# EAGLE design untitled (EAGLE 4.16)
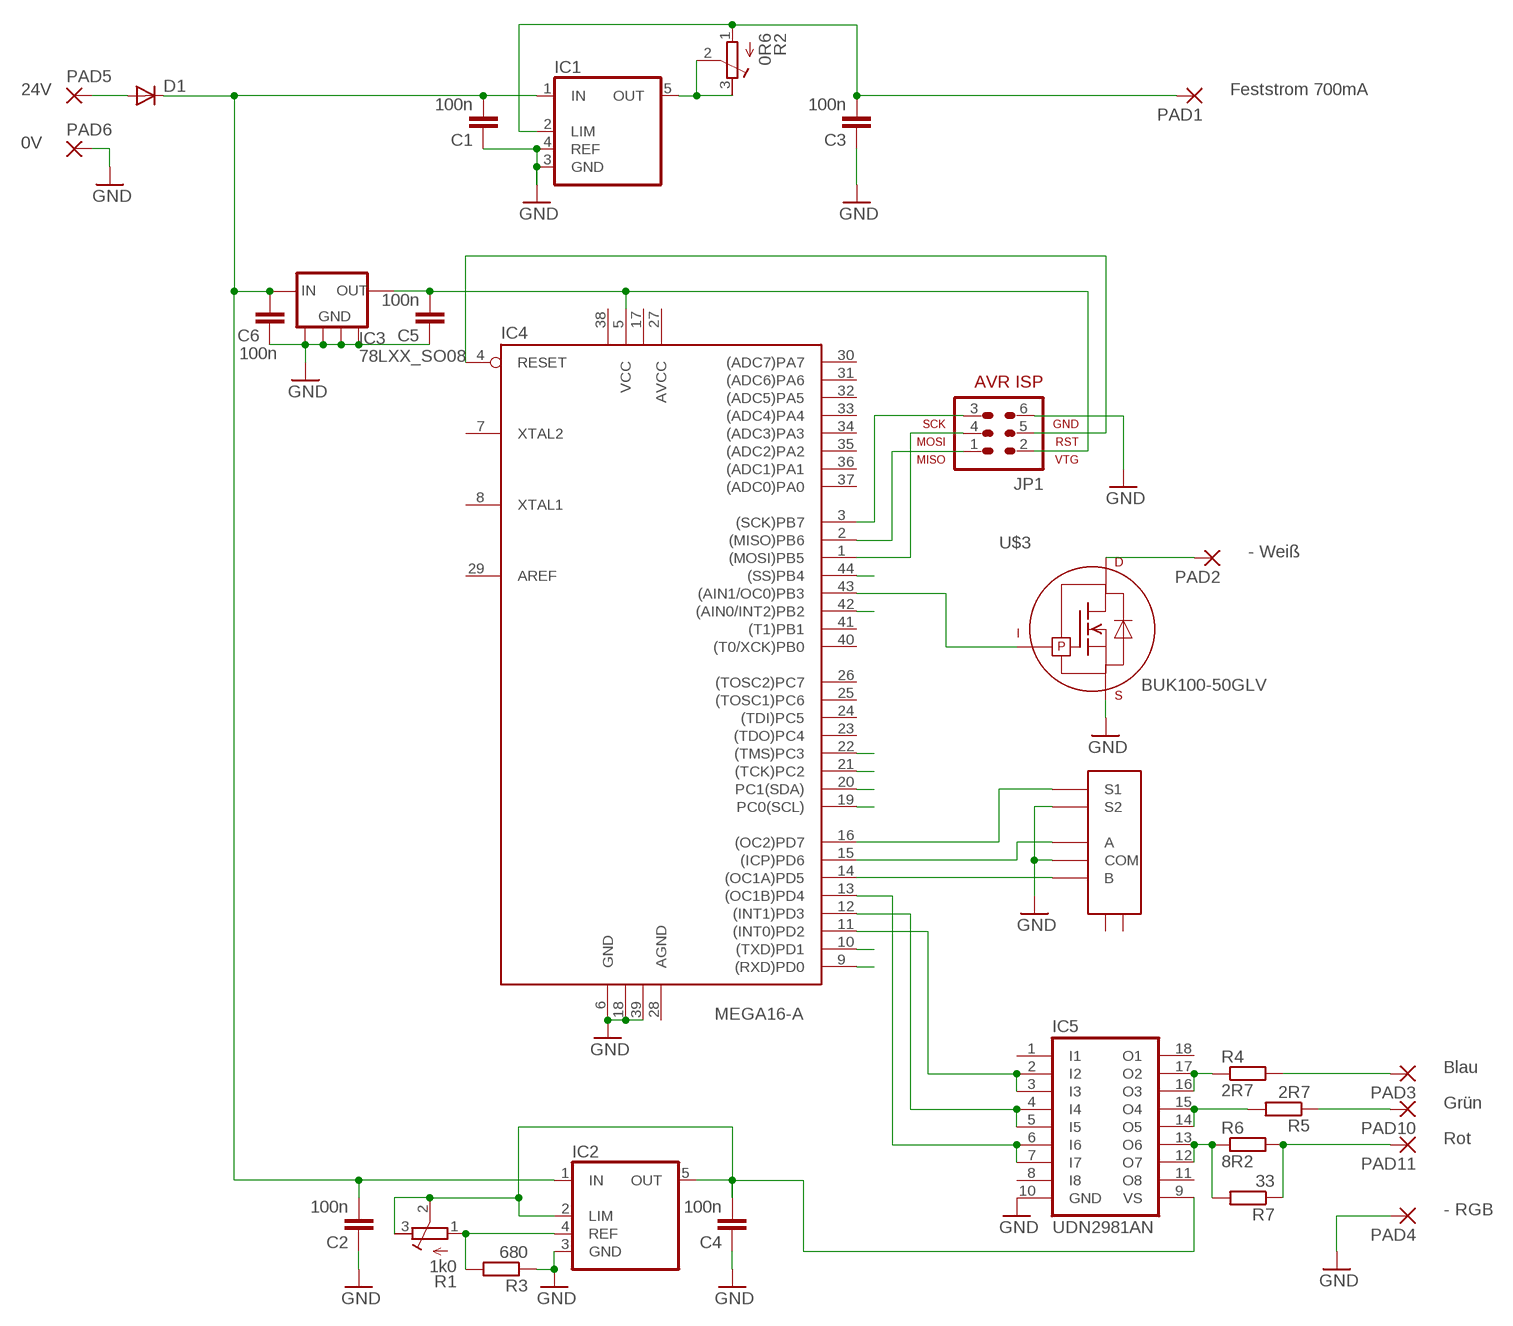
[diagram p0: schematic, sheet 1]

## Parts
C1  100n  C-EUC0603  [C0603]
C2  100n  C-EUC0603  [C0603]
C3  100n  C-EUC0603  [C0603]
C4  100n  C-EUC0603  [C0603]
C5  100n  C-EUC0603  [C0603]
C6  100n  C-EUC0603  [C0603]
D1  DIODE-D-12.5  [D-12.5]
IC1  L200  [L200S]
IC2  L200  [L200S]
IC3  78LXX_SO08  [SO08]
IC4  MEGA16-A  [TQFP44]
IC5  UDN2981AN  [DIL18]
JP1  AVR-ISP-6  [AVR-ISP-6]
PAD1  1,6/0,9  [1,6/0,9]
PAD2  1,6/0,9  [1,6/0,9]
PAD3  1,6/0,9  [1,6/0,9]
PAD4  1,6/0,9  [1,6/0,9]
PAD5  2,15/1,0  [2,15/1,0]
PAD6  2,15/1,0  [2,15/1,0]
PAD10  1,6/0,9  [1,6/0,9]
PAD11  1,6/0,9  [1,6/0,9]
R1  1k0  R-TRIMM64Z  [RTRIM64Z]
R2  0R6  R-TRIMM64Z  [RTRIM64Z]
R3  680  R-EU_R0805  [R0805]
R4  2R7  R-EU_0613/5V  [P0613V]
R5  2R7  R-EU_0613/5V  [P0613V]
R6  8R2  R-EU_0613/5V  [P0613V]
R7  33  R-EU_0204/2V  [0204V]
S1  INCREMENTALGEBER  [INCREMENTAL]
U$3  BUK100-50GLV  [TO220V]

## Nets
GND: C1.1 C2.1 C3.1 C4.1 C5.1 C6.1 IC1.3(GND) IC1.4(REF) IC2.3(GND) IC3.2(GND3) IC3.3(GND2) IC3.6(GND1) IC3.7(GND) IC4.6(GND) IC4.18(GND1) IC4.39(GND2) IC5.10(GND) JP1.6 PAD4.1(P) PAD6.1(P) R3.1 S1.COM S1.S2 U$3.3(S)
N$2: IC1.5(OUT) R2.2(S) R2.3(A)
N$3: IC2.4(REF) R1.1(E) R3.2
N$4: PAD2.1(P) U$3.2(D)
N$5: IC5.16(O3) IC5.17(O2) R4.1
N$6: C1.2 C2.2 C6.2 D1.C IC1.1(IN) IC2.1(IN) IC3.8(IN)
N$7: C4.2 IC2.2(LIM) IC2.5(OUT) IC5.9(VS) R1.2(S) R1.3(A)
N$8: IC5.12(O7) IC5.13(O6) R6.1 R7.2
N$9: C3.2 IC1.2(LIM) PAD1.1(P) R2.1(E)
N$10: C5.2 IC3.1(OUT) IC4.5(VCC) JP1.2
N$12: D1.A PAD5.1(P)
N$13: IC5.14(O5) IC5.15(O4) R5.2
N$14: IC4.19(PC0(SCL))
N$15: IC4.16((OC2)PD7) S1.S1
N$16: IC4.12((INT1)PD3) IC5.4(I4) IC5.5(I5)
N$17: PAD3.1(P) R4.2
N$18: PAD10.1(P) R5.1
N$19: PAD11.1(P) R6.2 R7.1
N$20: IC4.3((SCK)PB7) JP1.3
N$21: IC4.2((MISO)PB6) JP1.1
N$22: IC4.1((MOSI)PB5) JP1.4
N$23: IC4.20(PC1(SDA))
N$24: IC4.15((ICP)PD6) S1.A
N$25: IC4.4(RESET) JP1.5
N$26: IC4.21((TCK)PC2)
N$27: IC4.13((OC1B)PD4) IC5.6(I6) IC5.7(I7)
N$28: IC4.11((INT0)PD2) IC5.2(I2) IC5.3(I3)
N$30: IC4.10((TXD)PD1)
N$31: IC4.9((RXD)PD0)
N$32: IC4.22((TMS)PC3)
N$33: IC4.44((SS)PB4)
N$34: IC4.43((AIN1/OC0)PB3) U$3.1(G)
N$35: IC4.42((AIN0/INT2)PB2)
N$36: IC4.14((OC1A)PD5) S1.B
Unconnected: IC4.7(XTAL2) IC4.8(XTAL1) IC4.23((TDO)PC4) IC4.24((TDI)PC5) IC4.25((TOSC1)PC6) IC4.26((TOSC2)PC7) IC4.30((ADC7)PA7) IC4.31((ADC6)PA6) IC4.32((ADC5)PA5) IC4.33((ADC4)PA4) IC4.34((ADC3)PA3) IC4.35((ADC2)PA2) IC4.36((ADC1)PA1) IC4.37((ADC0)PA0) IC4.40((T0/XCK)PB0) IC4.41((T1)PB1) IC5.1(I1) IC5.8(I8) IC5.11(O8) IC5.18(O1) S1.GND(M) S1.GND@1(M)

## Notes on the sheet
- 24V | Feststrom 700mA
- 0V
- - Weiß
- Blau
- Grün
- Rot
- - RGB

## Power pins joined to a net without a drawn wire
AGND: IC4.28(AGND)
AREF: IC4.29(AREF)
AVCC: IC4.27(AVCC)
VCC1: IC4.17(VCC1)
VCC2: IC4.38(VCC2)

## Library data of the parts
C1-C6 = rcl:C-EU: CAPACITOR, European symbol
D1 = diode:DIODE-: DIODE
IC1 IC2 = v-reg:L200: VOLTAGE REGULATOR
IC3 = v-reg:78LXX_SO08: VOLTAGE REGULATOR IMax: 100mA
IC4 = atmel:MEGA16: MICROCONTROLLER 16 Kbytes FLASH 1 kbytes SRAM 512 bytes EEPROM USART 8-channel 10 bit ADC
IC5 = uln-udn:UDN2981A: DRIVER ARRAY
JP1 = atmel:AVR-ISP-6: AVR ISP-6 Serial Programming Header
PAD1-PAD4 PAD10 PAD11 = wirepad:1,6/0,9: THROUGH-HOLE PAD
PAD5 PAD6 = wirepad:2,15/1,0: THROUGH-HOLE PAD
R1 R2 = rcl:R-TRIMM: Trimm resistor
R3-R7 = rcl:R-EU_: RESISTOR, European symbol
S1 = Drehodierschalter:INCREMENTALGEBER
U$3 = transistor-fet:BUK100-50GL: N-Channel PowerMOS transistor Logic level TOPFET 50V; 13,5A; 125mOhm

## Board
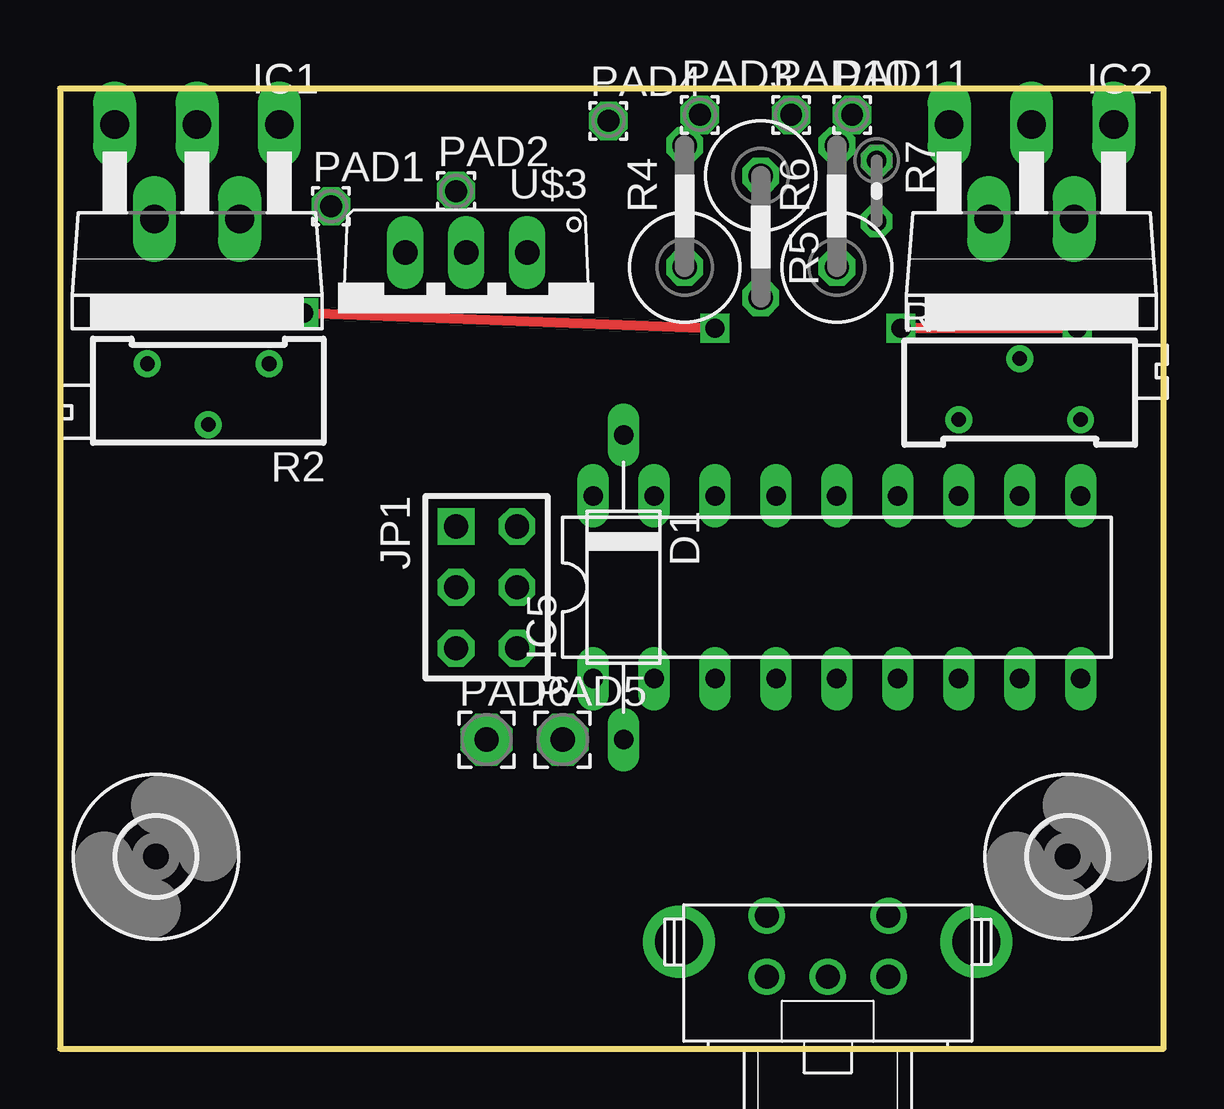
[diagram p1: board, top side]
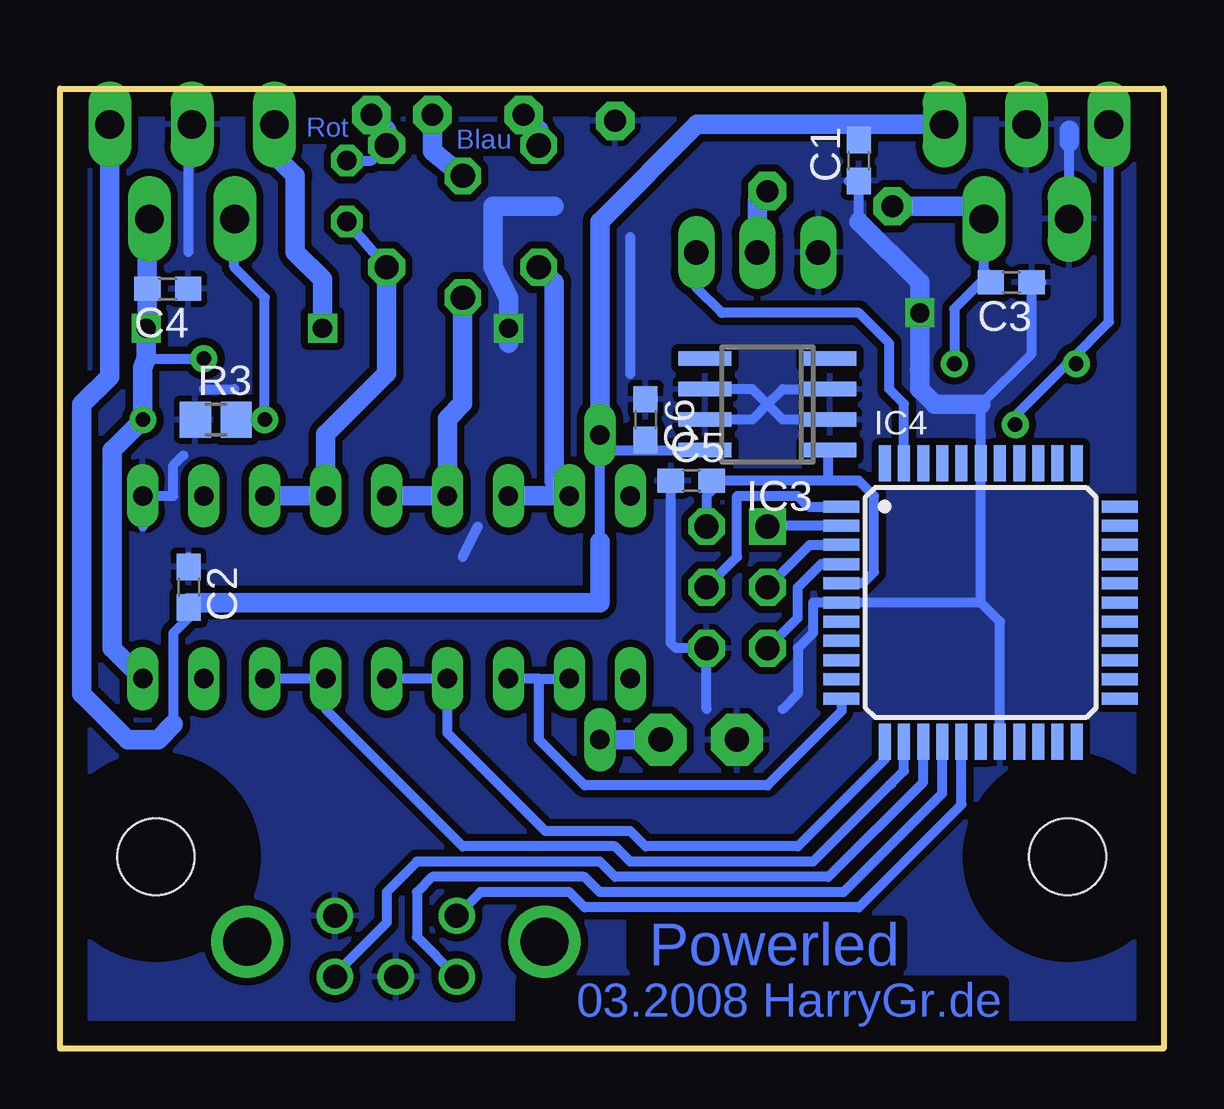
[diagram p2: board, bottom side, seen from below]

Size 46 x 40 mm. Coordinates in mm from the lower left corner, seen from the top.
Outline: 46,0 46,40 0,40 0,0 46,0
Copper layers (1*16): Top 0.035mm / dielectric 1.5mm / Bottom 0.035mm
Design rules "default": minimum track width 10mil, minimum drill 24mil, track to track 8mil, track to pad 8mil, pad to pad 8mil, via to via 8mil, smd to smd 8mil, copper to edge 40mil, drill to drill 8mil, minimum pad ring 10mil, minimum via ring 8mil, stop-mask expansion 4mil, vias tented up to drill 0mil, thermal gap 10mil
tRestrict: area 25.5,0 to 38.5,14.4; area 11.2,0 to 20.8,7.5

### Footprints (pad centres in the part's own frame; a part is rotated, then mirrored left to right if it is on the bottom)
C0603 = smd 1.1 x 1: 1 -0.85,0; 2 0.85,0
D-12.5 = drill 0.813 long: A 6.35,0; C -6.35,0
L200S = drill 1.194 long: 1 -3.429,-8.509; 2 -1.778,-4.572; 3 0,-8.509; 4 1.778,-4.572; 5 3.429,-8.509
SO08 = smd 0.6 x 2.2: 1 -1.905,-2.6; 2 -0.635,-2.6; 3 0.635,-2.6; 4 1.905,-2.6; 5 1.905,2.6; 6 0.635,2.6; 7 -0.635,2.6; 8 -1.905,2.6
TQFP44 = smd 1.5 x 0.5: 1 -5.8,4; 2 -5.8,3.2; 3 -5.8,2.4; 4 -5.8,1.6; 5 -5.8,0.8; 6 -5.8,0; 7 -5.8,-0.8; 8 -5.8,-1.6; 9 -5.8,-2.4; 10 -5.8,-3.2; 11 -5.8,-4; 23 5.8,-4; 24 5.8,-3.2; 25 5.8,-2.4; 26 5.8,-1.6; 27 5.8,-0.8; 28 5.8,0; 29 5.8,0.8; 30 5.8,1.6; 31 5.8,2.4; 32 5.8,3.2; 33 5.8,4 | smd 0.5 x 1.5: 12 -4,-5.8; 13 -3.2,-5.8; 14 -2.4,-5.8; 15 -1.6,-5.8; 16 -0.8,-5.8; 17 0,-5.8; 18 0.8,-5.8; 19 1.6,-5.8; 20 2.4,-5.8; 21 3.2,-5.8; 22 4,-5.8; 34 4,5.8; 35 3.2,5.8; 36 2.4,5.8; 37 1.6,5.8; 38 0.8,5.8; 39 0,5.8; 40 -0.8,5.8; 41 -1.6,5.8; 42 -2.4,5.8; 43 -3.2,5.8; 44 -4,5.8
DIL18 = drill 0.813 long: 1 -10.16,-3.81; 2 -7.62,-3.81; 3 -5.08,-3.81; 4 -2.54,-3.81; 5 0,-3.81; 6 2.54,-3.81; 7 5.08,-3.81; 8 7.62,-3.81; 9 10.16,-3.81; 10 10.16,3.81; 11 7.62,3.81; 12 5.08,3.81; 13 2.54,3.81; 14 0,3.81; 15 -2.54,3.81; 16 -5.08,3.81; 17 -7.62,3.81; 18 -10.16,3.81
AVR-ISP-6 = drill 1.016 square: 1 -2.54,-1.27 | drill 1.016 octagon: 2 -2.54,1.27; 3 0,-1.27; 4 0,1.27; 5 2.54,-1.27; 6 2.54,1.27
1,6/0,9 = drill 0.914 pad 1.6 octagon: 1 0,0
2,15/1,0 = drill 1.016 pad 2.159 octagon: 1 0,0
RTRIM64Z = drill 0.61 round: 1 0,-2.54; 2 -2.54,0; 3 0,2.54
R0805 = smd 1.3 x 1.5: 1 -0.85,0; 2 0.85,0
P0613V = drill 1.016 octagon: 1 -2.54,0; 2 2.54,0
0204V = drill 0.813 octagon: 1 -1.27,0; 2 1.27,0
INCREMENTAL = drill 1 round: A -2.54,0; B 2.54,0; COM 0,0; S1 -2.54,2.54; S2 2.54,2.54 | drill 2 round: GND -6.2,1.45; GND@1 6.2,1.45
3,2 = hole 3.2: 0,0
TO220V = drill 1.016 long: 1 -2.54,-2.54; 2 0,-2.54; 3 2.54,-2.54

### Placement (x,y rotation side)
C1  12.7,37.01 90 bottom
C2  40.64,19.23 270 bottom
C3  6.35,31.92 180 bottom
C4  41.51,31.66 180 bottom
C5  19.68,23.67 0 bottom
C6  21.59,26.21 270 bottom
D1  23.5,19.23 270 top
IC1  5.71,30 180 top
IC2  40.49,30 180 top
IC3  16.51,26.84 90 bottom
IC4  7.62,18.59 0 bottom
IC5  32.38,19.23 0 top
JP1  17.78,19.23 270 top
PAD1  11.29,35.1 0 top
PAD2  16.51,35.73 0 top
PAD3  26.67,38.91 0 top
PAD4  22.86,38.66 0 top
PAD5  20.95,12.88 0 top
PAD6  17.78,12.88 0 top
PAD10  30.48,38.91 0 top
PAD11  33.02,38.91 0 top
R1  40.01,26.21 270 top
R2  6.18,28.54 90 top
R3  39.51,26.21 0 bottom
R4  26.04,35.1 90 top
R5  29.21,33.83 270 top
R6  32.38,35.1 90 top
R7  34.04,35.73 270 top
S1  32,3 0 top
U$1  [3,2]  4,8 0 top
U$2  [3,2]  42,8 0 top
U$3  16.93,30.63 180 top

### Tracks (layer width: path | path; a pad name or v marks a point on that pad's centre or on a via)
GND  (via drill 0.8)
  Top 0.406: v10.16,30.66 v27.3,30.02
  Bottom 0.406: IC2.3 40.49,38.42 40.64,38.27 40.64,33.2 | 40.64,19.86 C2.1 40.64,20.5 | 42.55,21.77 IC5.10 41.27,23.04 41.27,24.3 40.85,24.73 | 40.01,27.48 38.73,27.48 | 5.08,31.92 C3.1 5.5,28.96 7.62,26.84 IC4.39 7.62,18.59 | 3.93,33.07 IC1.4 3.93,37.76 | 5.71,38.27 5.71,38.28 IC1.3 | 29.21,20.5 28.57,21.77 | 14.59,33.17 13.97,33.2 | 12.7,34.47 C1.1 13.12,36.16 | 16.51,26.84 17.14,27.48 IC3.6 | IC3.7 17.14,26.21 16.51,26.84 | IC3.3 15.88,27.48 16.51,26.84 | IC3.2 15.88,26.21 16.51,26.84 | 22.23,28.11 22.23,33.83 | IC4.18 6.82,17.79 7.62,18.59 | 7.62,18.59 IC4.6 14.61,18.59 14.61,17.32 15.24,16.68 15.24,14.78 15.88,14.14 | 10.16,28.11 10.38,28.33 | C5.1 20.54,16.9 20.32,16.68 JP1.6 19.05,14.14
  Bottom 0.813: 7.62,26.84 9.53,26.84 10.16,27.48 10.16,28.11 v10.16,30.66 10.16,31.92 12.7,34.47 | U$3.3 14.59,33.17 | 27.3,29.38 v27.3,30.02 27.3,31.29 27.94,32.56 27.94,35.1 25.4,35.1 | 3.93,37.76 3.93,38.27
  pour Bottom (isolate 0.305): 0,0.17 0,39.55 45.72,39.55 45.72,0.17
N$1  (via drill 1.2)
  other vias: 4,8
N$2
  Bottom 0.406: IC1.5 2.28,30.28 3.81,28.75 | 3.81,28.75 3.64,28.58 R2.3 | R2.2 6.18,26.38 3.81,28.75
N$3
  Bottom 0.406: IC2.4 38.73,34.55 38.73,32.56 37.47,31.29 R1.1 38.73,26.21 38.62,26.07 R3.2
N$4
  Bottom 0.813: U$3.2 16.93,35.31 PAD2.1
N$5
  Bottom 0.813: IC5.16 IC5.17 25.4,23.67 25.4,31.92 R4.1
N$6
  Bottom 0.406: 41.27,13.51 41.27,17.32 40.64,17.95 C2.2 40.64,18.59 | 12.7,38.51 C1.2 | 21.59,24.94 22.86,24.94 D1.C 23.5,21.13 | 21.59,24.94 IC3.8 | 21.59,24.94 C6.2
  Bottom 0.813: IC2.1 43.92,28.01 45.09,26.84 45.09,14.78 43.18,12.88 41.91,12.88 41.27,13.51 | 40.64,18.59 23.5,18.59 23.5,21.13 | D1.C 23.5,34.47 19.45,38.51 12.7,38.51 9.76,38.51 9.14,38.52 IC1.1
N$7  (via drill 0.8)
  Top 0.406: v42.41,30.02 v35.06,30.02
  Bottom 0.406: 42.41,28.75 R1.2
  Bottom 0.813: IC5.9 43.81,16.68 43.81,24.94 R1.3 42.55,28.36 42.41,28.75 v42.41,30.02 42.48,30.02 | v35.06,30.02 35.06,32.06 36.2,33.2 36.2,36.37 37.07,37.24 IC2.5 | 42.48,30.02 42.5,30 | 42.48,30.02 42.35,30.15 C4.2 42.35,34.4 42.25,34.5 42.27,34.52 IC2.2
N$8
  Bottom 0.406: R6.1 R7.2
  Bottom 0.813: IC5.12 IC5.13 34.92,25.59 32.38,28.14 R6.1
N$9
  Bottom 0.406: 7.62,34.47 7.51,34.57 IC1.2 7.49,32.43 6.99,31.92 C3.2 7.62,31.92 8.72,30.83 R2.1
  Bottom 0.813: PAD1.1 8.26,35.1 7.62,34.47
N$10
  Bottom 0.406: JP1.2 19.05,23.04 18.41,23.67 | 13.97,23.67 18.41,23.67 | 13.97,23.67 13.97,24.94 IC3.1 | 13.97,23.67 12.7,23.67 12.06,23.04 12.06,19.86 12.54,19.39 IC4.5 | 18.41,23.67 C5.2
N$11  (via drill 1.2)
  other vias: 42,8
N$12
  Bottom 0.813: PAD5.1 D1.A
N$13
  Bottom 0.813: IC5.14 IC5.15 29.84,26.25 29.21,26.89 R5.2
N$15
  Bottom 0.406: S1.S1 28.48,6.53 24.77,6.53 24.13,5.89 12.7,5.89 8.42,10.17 IC4.16
N$16
  Bottom 0.406: IC5.5 IC5.4 29.84,13.14 25.77,9.06 22.23,9.06 21.59,8.43 15.24,8.43 11.62,12.05 IC4.12
N$17
  Bottom 0.813: R4.2 26.04,38.27 PAD3.1
N$18
  Bottom 0.813: R5.1 30.46,37.39 PAD10.1
N$19
  Bottom 0.406: R7.1 33.02,37.01 R6.2
  Bottom 0.813: R6.2 32.38,38.27 PAD11.1
N$20
  Bottom 0.406: IC4.3 14.74,20.99 JP1.3
N$21
  Bottom 0.406: IC4.2 16.48,21.79 JP1.1
N$22
  Bottom 0.406: IC4.1 14.79,22.59 15.24,23.04 17.78,23.04 17.78,20.5 JP1.4
N$24
  Bottom 0.406: S1.A 31.11,4.66 31.11,6.53 30.48,7.16 24.13,7.16 23.5,6.53 13.34,6.53 9.22,10.64 IC4.15
N$25
  Bottom 0.406: IC4.4 14.28,20.19 15.24,19.23 15.24,17.95 JP1.5
N$27
  Bottom 0.406: 11.43,10.97 14.61,7.79 22.23,7.79 22.86,8.43 29.21,8.43 34.92,14.14 IC5.6 IC5.7 | 11.43,10.97 11.29,11.11 | IC4.13 10.82,11.58 11.43,10.97
N$28
  Bottom 0.406: 26.04,15.41 26.04,12.88 24.13,10.97 16.51,10.97 13.42,14.06 IC4.11 | 26.04,15.41 IC5.2 | 26.04,15.41 IC5.3
N$34
  Bottom 0.406: U$3.1 19.48,31.72 18.41,30.66 12.7,30.66 11.43,29.38 11.43,27.48 10.82,26.87 IC4.43
N$36
  Bottom 0.406: S1.B 34.54,3.1 32.38,5.26 32.38,6.53 31.11,7.79 23.5,7.79 22.86,7.16 13.97,7.16 10.02,11.11 IC4.14

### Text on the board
Bottom: Rot | Blau | Powerled | 03.2008 HarryGr.de
Document: n-Fet isolieren | Drehgeber auf max 13 feilen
